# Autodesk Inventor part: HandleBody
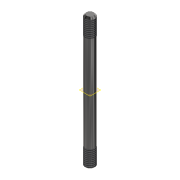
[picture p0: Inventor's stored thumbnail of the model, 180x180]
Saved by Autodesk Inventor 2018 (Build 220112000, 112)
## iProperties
Created: 2011-02
Part Number: HandleBody
Material: Generic
Document SubType Name: Modeling
Designer: landrews
Density: 1 g/cm^3
Appearance: Knurled 45
Mass: 2.24519 g
Surface Area: 15.3983 cm^2
Volume: 2.24519 cm^3
Author: landrews
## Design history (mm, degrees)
sketch "Sketch1"
  geometry: C1 r 3 at (0, 0); 1 further point
  constraints: 1 centre point, 1 coincident
  dimensions: "d0" = 6 diameter of C1
extrude "Extrusion1" new body sketch "Sketch1" stored distance "d1" = 80; taper "d2" = 0 deg
chamfer "Chamfer2" distance "d10" = 1; stored, may be unused: second distance "d11" = 2, angle "d12" = 45 deg
thread "Thread1" dims "d13" = 10, "d14" = 0
thread "Thread2" dims "d15" = 10, "d16" = 0
body "Solid1"
